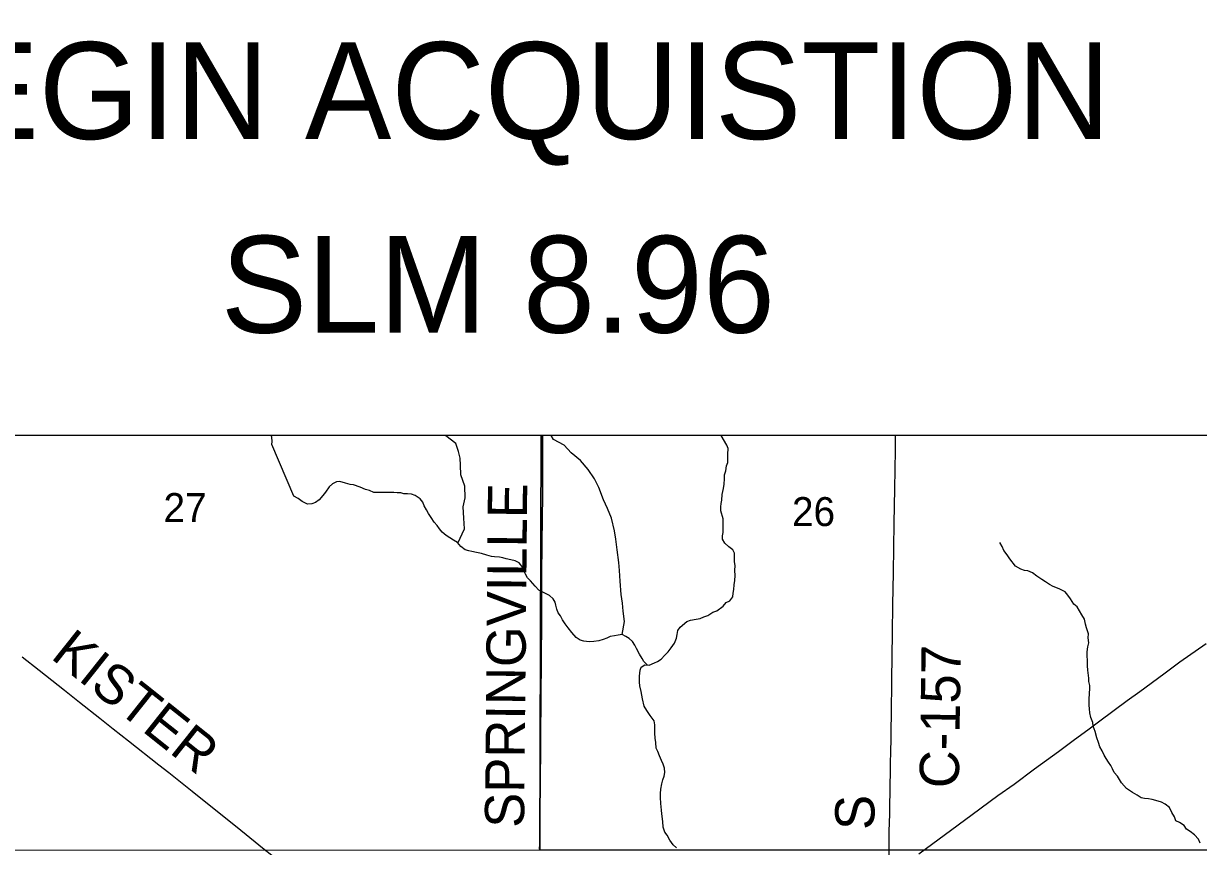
# Model space of a CAD drawing. Extents: x 0 to 34, y 0 to 22.
# Drawn here: x 2.995 to 4.694, y 16.277 to 17.466 of the extents above; entities that cross this region are included whole.
import ezdxf

# ---------------------------------------------------------------- set-up
doc = ezdxf.new("R2010")
doc.units = 0
for name, color, linetype in [('GM_X_County_Road', 7, 'Continuous'), ('GM_X_County_Road_Text', 7, 'Continuous'), ('GM_X_Minor_River', 7, 'Continuous'), ('GM_X_Section', 7, 'Continuous'), ('GM_X_Section_Text', 7, 'Continuous'), ('GM_X_State_Route', 7, 'Continuous'), ('GM_X_Township_Road', 7, 'Continuous'), ('GM_X_Township_Road_Text', 7, 'Continuous'), ('SH_Text', 7, 'Continuous')]:
    doc.layers.add(name, color=color, linetype=linetype)

msp = doc.modelspace()

# ---------------------------------------------------------------- linework, layer by layer
at = {"layer": 'GM_X_County_Road'}
msp.add_lwpolyline([(4.2461, 16.2345), (4.2465, 16.2795), (4.2467, 16.2981), (4.2474, 16.324), (4.2475, 16.3396), (4.2478, 16.3527), (4.2481, 16.3635), (4.2481, 16.3706), (4.2483, 16.3786), (4.2483, 16.3867), (4.2484, 16.3987), (4.2487, 16.412), (4.2492, 16.4335), (4.2493, 16.446), (4.2497, 16.4677), (4.2504, 16.5174), (4.2515, 16.5857), (4.252, 16.6261), (4.2526, 16.6727), (4.2537, 16.7442), (4.2546, 16.7938), (4.2555, 16.8498), (4.2557, 16.8709)], dxfattribs=at)
at = {"layer": 'GM_X_Minor_River'}
msp.add_line((3.6056, 16.8706), (3.6055, 16.8709), dxfattribs=at)
for points in [[(3.354, 16.8579), (3.3543, 16.8621), (3.3539, 16.8682), (3.3529, 16.8709)], [(3.8967, 16.5391), (3.8919, 16.5439), (3.8892, 16.5485), (3.8854, 16.5546), (3.8812, 16.5629), (3.8785, 16.5679), (3.8754, 16.5728), (3.8705, 16.5774), (3.8659, 16.5801), (3.8605, 16.5831), (3.8548, 16.582), (3.8495, 16.5812), (3.8433, 16.5801), (3.8384, 16.5778), (3.8331, 16.5759), (3.8266, 16.574), (3.8193, 16.5729), (3.8128, 16.5725), (3.8052, 16.5736), (3.7999, 16.5748), (3.7941, 16.579), (3.7876, 16.5862), (3.7823, 16.5926), (3.778, 16.5984), (3.7742, 16.6044), (3.7712, 16.6101), (3.7681, 16.6147), (3.7658, 16.62), (3.7646, 16.6254), (3.7635, 16.6299), (3.7608, 16.6349), (3.7554, 16.6394), (3.7505, 16.6417), (3.7447, 16.6448), (3.7398, 16.6474), (3.7344, 16.6528), (3.7279, 16.6607), (3.7237, 16.6653), (3.7206, 16.6703), (3.7183, 16.6752), (3.7168, 16.6798), (3.7114, 16.6866), (3.7057, 16.6897), (3.6996, 16.6912), (3.6927, 16.6923), (3.6878, 16.6938), (3.6828, 16.695), (3.6759, 16.6954), (3.6713, 16.6961), (3.6648, 16.698), (3.6572, 16.7003), (3.65, 16.7015), (3.6431, 16.703), (3.6385, 16.7041), (3.6335, 16.7057), (3.627, 16.7102), (3.6221, 16.7163), (3.6163, 16.7194), (3.611, 16.7228), (3.606, 16.7262), (3.6003, 16.7312), (3.5961, 16.7361), (3.593, 16.7407), (3.5884, 16.7456), (3.5842, 16.7525), (3.5804, 16.7582), (3.5773, 16.7635), (3.5742, 16.7692), (3.5723, 16.7745), (3.5685, 16.7791), (3.5612, 16.784), (3.5559, 16.7859), (3.5498, 16.7867), (3.5448, 16.7867), (3.5402, 16.7879), (3.5349, 16.7879), (3.5303, 16.7886), (3.5211, 16.7882), (3.515, 16.7886), (3.5013, 16.7886), (3.4952, 16.7913), (3.4895, 16.7928), (3.4814, 16.7963), (3.4719, 16.7993), (3.4669, 16.8001), (3.4604, 16.802), (3.452, 16.8043), (3.4471, 16.8039), (3.4417, 16.8012), (3.4368, 16.7967), (3.4315, 16.7891), (3.4276, 16.7841), (3.4223, 16.778), (3.417, 16.7742), (3.4116, 16.772), (3.4055, 16.7716), (3.3979, 16.7754), (3.3918, 16.78), (3.3857, 16.783), (3.354, 16.8579)], [(3.623, 16.7151), (3.6326, 16.736), (3.6314, 16.7512), (3.6306, 16.7675), (3.6336, 16.7808), (3.6331, 16.7978), (3.627, 16.8141), (3.6266, 16.8278), (3.6262, 16.8381), (3.6239, 16.8479), (3.6197, 16.8593), (3.6056, 16.8706)], [(3.7765, 16.8571), (3.7613, 16.8653), (3.7579, 16.8709)], [(3.8605, 16.5831), (3.8638, 16.602), (3.8619, 16.6168), (3.8607, 16.6282), (3.8591, 16.6411), (3.8575, 16.6604), (3.8567, 16.6756), (3.8555, 16.687), (3.8532, 16.7056), (3.8512, 16.7208), (3.8493, 16.7329), (3.8451, 16.7515), (3.8393, 16.7655), (3.8336, 16.7776), (3.8267, 16.7958), (3.8202, 16.8083), (3.8111, 16.8216), (3.8, 16.8345), (3.7868, 16.8458), (3.7765, 16.8571)], [(4.0084, 16.8081), (4.0084, 16.8138), (4.0103, 16.8199), (4.0114, 16.8268), (4.013, 16.8317), (4.0133, 16.8374), (4.0133, 16.8439), (4.0137, 16.8519), (4.0118, 16.8568), (4.0036, 16.8709)], [(3.9391, 16.2747), (3.9341, 16.2788), (3.9292, 16.2857), (3.9253, 16.2929), (3.9223, 16.2975), (3.9199, 16.3047), (3.9192, 16.3127), (3.918, 16.3237), (3.9172, 16.3294), (3.9164, 16.3389), (3.916, 16.3477), (3.916, 16.3534), (3.9164, 16.3595), (3.9179, 16.3671), (3.9194, 16.3732), (3.9213, 16.3781), (3.922, 16.3838), (3.9217, 16.3899), (3.9197, 16.3956), (3.9174, 16.4009), (3.9144, 16.4078), (3.9121, 16.4142), (3.9098, 16.4188), (3.909, 16.4268), (3.9082, 16.4332), (3.9078, 16.4405), (3.9078, 16.4526), (3.9066, 16.4583), (3.9009, 16.466), (3.8959, 16.4732), (3.8921, 16.4793), (3.8897, 16.4903), (3.8878, 16.5009), (3.8859, 16.5089), (3.8855, 16.5143), (3.8855, 16.523), (3.8866, 16.5314), (3.8877, 16.5359), (3.8931, 16.5393), (3.8995, 16.539), (3.9072, 16.542), (3.9117, 16.5439), (3.9167, 16.5473), (3.922, 16.5534), (3.927, 16.5583), (3.9315, 16.5637), (3.9361, 16.5705), (3.9391, 16.5777), (3.9399, 16.5831), (3.941, 16.5891), (3.9444, 16.5937), (3.954, 16.6017), (3.9593, 16.604), (3.9673, 16.6055), (3.973, 16.6062), (3.9784, 16.6089), (3.9845, 16.6104), (3.9917, 16.6153), (3.9971, 16.6172), (4.0066, 16.6241), (4.0108, 16.6294), (4.0161, 16.6317), (4.0203, 16.6378), (4.021, 16.6427), (4.0218, 16.6484), (4.0225, 16.6549), (4.0233, 16.6613), (4.0237, 16.6686), (4.0233, 16.6758), (4.0236, 16.683), (4.0228, 16.688), (4.0228, 16.7009), (4.0205, 16.7055), (4.0148, 16.71), (4.0087, 16.7153), (4.0056, 16.7211), (4.0056, 16.7256), (4.0063, 16.7306), (4.0063, 16.7355), (4.0067, 16.7401), (4.0067, 16.7503), (4.0032, 16.7621), (4.0032, 16.7678), (4.0036, 16.7724), (4.0043, 16.7773), (4.0051, 16.7857), (4.0069, 16.7941), (4.0077, 16.8005), (4.0084, 16.8081)], [(4.6962, 16.2815), (4.6936, 16.2872), (4.6878, 16.2933), (4.6817, 16.2982), (4.6763, 16.3016), (4.6729, 16.307), (4.6664, 16.3111), (4.661, 16.3138), (4.6591, 16.3195), (4.6553, 16.326), (4.6518, 16.3328), (4.6457, 16.3378), (4.6404, 16.3408), (4.6354, 16.3423), (4.627, 16.3446), (4.6217, 16.3454), (4.6159, 16.3462), (4.611, 16.3469), (4.6049, 16.3507), (4.5984, 16.3545), (4.5896, 16.3606), (4.5823, 16.3686), (4.5769, 16.3781), (4.572, 16.3838), (4.5693, 16.3888), (4.567, 16.3937), (4.5635, 16.3987), (4.5601, 16.404), (4.5574, 16.4089), (4.5547, 16.415), (4.5509, 16.4207), (4.5493, 16.4268), (4.547, 16.4337), (4.5443, 16.4428), (4.5417, 16.4508), (4.5409, 16.4561), (4.5382, 16.4629), (4.5367, 16.4698), (4.5363, 16.4759), (4.5359, 16.4812), (4.5355, 16.4892), (4.5362, 16.4983), (4.5366, 16.5044), (4.5366, 16.5093), (4.535, 16.515), (4.535, 16.52), (4.5338, 16.5314), (4.5334, 16.5379), (4.5334, 16.5462), (4.5326, 16.5519), (4.5326, 16.558), (4.5338, 16.5652), (4.5353, 16.5713), (4.5345, 16.5785), (4.5349, 16.5842), (4.5318, 16.593), (4.5306, 16.5979), (4.5291, 16.6052), (4.5252, 16.6116), (4.5184, 16.623), (4.5134, 16.6268), (4.5088, 16.6348), (4.505, 16.6398), (4.5011, 16.6447), (4.4923, 16.6493), (4.4836, 16.6527), (4.4782, 16.6554), (4.4725, 16.6592), (4.4671, 16.6626), (4.4602, 16.6676), (4.4537, 16.6721), (4.4472, 16.6752), (4.4423, 16.6759), (4.4369, 16.6775), (4.4293, 16.6817), (4.4209, 16.6923), (4.417, 16.6984), (4.4121, 16.7045), (4.4098, 16.7102), (4.4063, 16.7163)]]:
    msp.add_lwpolyline(points, dxfattribs=at)
at = {"layer": 'GM_X_Section'}
for points in [[(2.7176, 16.8709), (2.7146, 16.2714), (3.7413, 16.2718), (3.7435, 16.8709)], [(3.7435, 16.8709), (3.7413, 16.2718), (4.754, 16.2718), (4.7564, 16.8709)]]:
    msp.add_lwpolyline(points, close=True, dxfattribs=at)
at = {"layer": 'GM_X_State_Route'}
msp.add_lwpolyline([(4.2893, 16.2658), (4.3463, 16.3079), (4.3664, 16.3229), (4.4037, 16.3503), (4.4271, 16.3668), (4.4565, 16.389), (4.4912, 16.4141), (4.5146, 16.4312), (4.5338, 16.4455), (4.5512, 16.4583), (4.5909, 16.4875), (4.6092, 16.5009), (4.6435, 16.5264), (4.6669, 16.5434), (4.705, 16.5703)], dxfattribs=at)
at = {"layer": 'GM_X_Township_Road'}
for points in [[(3.7411, 16.2728), (3.7413, 16.2805), (3.7413, 16.2991), (3.7413, 16.3168), (3.7414, 16.3277), (3.7415, 16.3419), (3.7421, 16.3587), (3.7425, 16.3782), (3.7428, 16.4125), (3.7428, 16.4339), (3.7429, 16.4463), (3.7432, 16.4805), (3.744, 16.5581), (3.7442, 16.5922), (3.7442, 16.6108), (3.7444, 16.6326), (3.7444, 16.6481), (3.7444, 16.6667), (3.7444, 16.6853), (3.7445, 16.6977), (3.7446, 16.7163), (3.7455, 16.7846), (3.7457, 16.8249), (3.7456, 16.8404), (3.7456, 16.8709)], [(2.9929, 16.5508), (3.0173, 16.5315), (3.0539, 16.5027), (3.0758, 16.4853), (3.105, 16.4623), (3.1244, 16.4468), (3.1464, 16.4296), (3.1902, 16.3949), (3.2049, 16.3834), (3.2386, 16.3565), (3.3089, 16.3001), (3.3427, 16.273), (3.3888, 16.2364), (3.4567, 16.1818), (3.4802, 16.1622), (3.5239, 16.127), (3.5454, 16.1092), (3.6035, 16.0626), (3.6228, 16.0469), (3.6491, 16.025), (3.6755, 16.0037), (3.7046, 15.9808), (3.7245, 15.9654), (3.7353, 15.9577)]]:
    msp.add_lwpolyline(points, dxfattribs=at)
at = {"layer": 'SH_Text'}
msp.add_lwpolyline([(2.5841, 17.5881), (4.804, 17.5881), (4.804, 16.8709), (2.5841, 16.8709)], close=True, dxfattribs=at)

# ---------------------------------------------------------------- texts
at = {"layer": 'GM_X_County_Road_Text'}
for s, height, rotation, p in [('C-157', 0.05682, 89.1819, (4.3472, 16.3606)), ('S', 0.0568, 90, (4.2253, 16.3006))]:
    msp.add_text(s, height=height, rotation=rotation, dxfattribs=at).set_placement(p)
at = {"layer": 'GM_X_Section_Text'}
for s, p in [('27', (3.1972, 16.7457)), ('26', (4.106, 16.7399))]:
    msp.add_text(s, height=0.04186, rotation=0, dxfattribs=at).set_placement(p)
at = {"layer": 'GM_X_Township_Road_Text'}
for s, height, rotation, p in [('SPRINGVILLE', 0.056818, 89.4704, (3.7186, 16.3035)), ('KISTER', 0.05682, 321.459, (3.0325, 16.5497))]:
    msp.add_text(s, height=height, rotation=rotation, dxfattribs=at).set_placement(p)
at = {"layer": 'SH_Text'}
for s, p in [('BEGIN ACQUISTION', (2.7672, 17.2995)), ('SLM 8.96', (3.28, 17.0195))]:
    msp.add_text(s, height=0.14, dxfattribs=at).set_placement(p)

doc.saveas('drawing.dxf')
